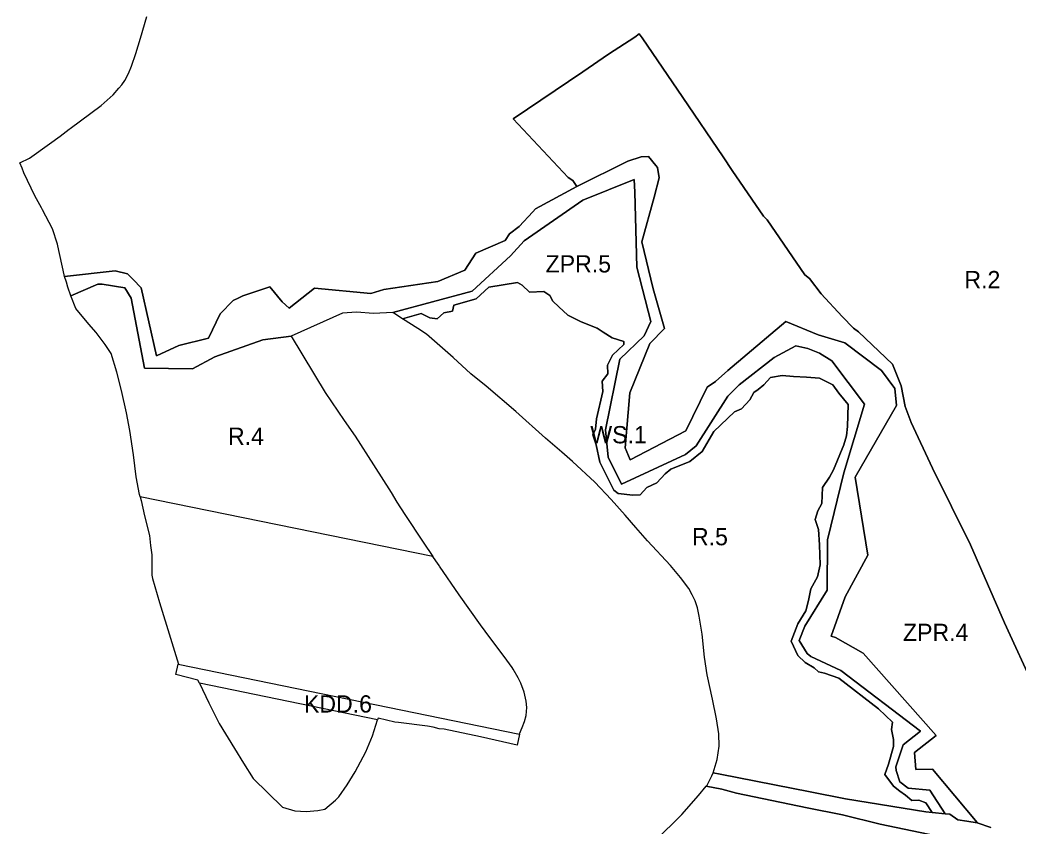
# Model space of a CAD drawing. Extents: x 7422965 to 7424741, y 5551047 to 5553849.
# Drawn here: x 7423072 to 7423766, y 5552892 to 5553453 of the extents above; entities that cross this region are included whole.
import ezdxf

# ---------------------------------------------------------------- set-up
doc = ezdxf.new("R2010")
doc.units = 0
for name, color, linetype in [('linie_rozgraniczajace', 7, 'Continuous'), ('oznaczenia_przeznaczen', 7, 'Continuous'), ('TR_Wydzielone z planu orzeczeniem sądu z 15_07_2011', 7, 'Continuous')]:
    doc.layers.add(name, color=color, linetype=linetype)

msp = doc.modelspace()

# ---------------------------------------------------------------- linework, layer by layer
at = {"layer": 'linie_rozgraniczajace'}
for points in [[(7423072.08, 5553353.5), (7423078.79, 5553356.75), (7423092.7, 5553366.75), (7423100.01, 5553372), (7423106.17, 5553376.96), (7423107.04, 5553377.34), (7423128.51, 5553393.48), (7423136.81, 5553400.87), (7423140.75, 5553405.35), (7423142.84, 5553407.78), (7423144.94, 5553410.78), (7423147.58, 5553415.55), (7423149.53, 5553420.67), (7423152.54, 5553429.58), (7423155.87, 5553440.27), (7423160.29, 5553455.14)], [(7423499.29, 5553440.9), (7423481.05, 5553429.11), (7423463.31, 5553416.76), (7423414.82, 5553384.08), (7423453.09, 5553343.43), (7423456.21, 5553341.18), (7423459.15, 5553337.18), (7423430.34, 5553321.61), (7423428.42, 5553319.38), (7423418.91, 5553309.19), (7423412.34, 5553304.21), (7423409.29, 5553299.45), (7423388.77, 5553290.77), (7423381.2, 5553278.79), (7423362.52, 5553270.91), (7423324.94, 5553265.51), (7423315.78, 5553262.78), (7423276.81, 5553266.37), (7423259.19, 5553252.57), (7423254.3, 5553256.83), (7423245.71, 5553267.27), (7423226.88, 5553260.98), (7423224.13, 5553259.62), (7423220.24, 5553257.7), (7423211.11, 5553248.57), (7423203.06, 5553231.66), (7423182.5, 5553226.56), (7423167, 5553219.27), (7423156.4, 5553266.58), (7423150.84, 5553272.48), (7423146.73, 5553276.28), (7423138.26, 5553278.44), (7423103.11, 5553274.39), (7423102.71, 5553275.62), (7423098.49, 5553295.91), (7423098.27, 5553296.97), (7423094.68, 5553307.7), (7423087.84, 5553320.86), (7423087.11, 5553322.16), (7423082.41, 5553330.54), (7423074.79, 5553346.6), (7423073.55, 5553349.77), (7423072.08, 5553353.5)], [(7423746.77, 5552891.46), (7423737.23, 5552894.78), (7423737.17, 5552894.79), (7423737.17, 5552894.81), (7423706.29, 5552932.02), (7423694.53, 5552931.69), (7423693.58, 5552943.53), (7423708.83, 5552955.35), (7423657.92, 5553012.63), (7423638.79, 5553023.62), (7423635.83, 5553024.45), (7423645.43, 5553051.8), (7423661.31, 5553080.78), (7423652.55, 5553134.99), (7423681.22, 5553184.74), (7423680.11, 5553196.68), (7423670.75, 5553209.05), (7423645.21, 5553228.49), (7423626.82, 5553233.84), (7423604.21, 5553243.11), (7423563.86, 5553209.12), (7423555.48, 5553201.53), (7423549.71, 5553197.54), (7423534.68, 5553167.09), (7423496, 5553147.04), (7423492.62, 5553155.4), (7423495.83, 5553193.64), (7423509.78, 5553227.89), (7423519.98, 5553238.33), (7423512.06, 5553266), (7423504.23, 5553298.7), (7423512.82, 5553329.66), (7423516.18, 5553343.05), (7423515.17, 5553350.25), (7423513.9, 5553351.61), (7423508.83, 5553357.89), (7423503.73, 5553357.8), (7423494.4, 5553354.63), (7423459.15, 5553337.18), (7423456.21, 5553341.18), (7423453.09, 5553343.43), (7423414.82, 5553384.08), (7423463.31, 5553416.76), (7423481.05, 5553429.11), (7423499.29, 5553440.9), (7423502.44, 5553443.28), (7423504.47, 5553440.43), (7423532.63, 5553399.02), (7423560.71, 5553357.68), (7423566.94, 5553348.25), (7423588.8, 5553316.54), (7423591.19, 5553313.83), (7423617.43, 5553275.54), (7423620.71, 5553273.22), (7423628.93, 5553262.45), (7423643.36, 5553246.77), (7423651.33, 5553238.66), (7423654.74, 5553235.94), (7423678.4, 5553213.45), (7423684.3, 5553198.56), (7423687.21, 5553184.11), (7423691.28, 5553172.9), (7423706.1, 5553141.25), (7423732.58, 5553087.91), (7423756.29, 5553033.78), (7423777.38, 5552987.86)], [(7423777.38, 5552987.86), (7423756.29, 5553033.78), (7423732.58, 5553087.91), (7423706.1, 5553141.25), (7423691.28, 5553172.9), (7423687.21, 5553184.11), (7423684.3, 5553198.56), (7423678.4, 5553213.45), (7423654.74, 5553235.94), (7423651.33, 5553238.66), (7423643.36, 5553246.77), (7423628.93, 5553262.45), (7423620.71, 5553273.22), (7423617.43, 5553275.54), (7423591.19, 5553313.83), (7423588.8, 5553316.54), (7423566.94, 5553348.25), (7423560.71, 5553357.68), (7423532.63, 5553399.02), (7423504.47, 5553440.43), (7423502.44, 5553443.28), (7423499.29, 5553440.9)], [(7423103.11, 5553274.39), (7423138.26, 5553278.44), (7423146.73, 5553276.28), (7423150.84, 5553272.48), (7423156.4, 5553266.58), (7423167, 5553219.27), (7423182.5, 5553226.56), (7423203.06, 5553231.66), (7423211.11, 5553248.57), (7423220.24, 5553257.7), (7423224.13, 5553259.62), (7423226.88, 5553260.98), (7423245.71, 5553267.27), (7423254.3, 5553256.83), (7423259.19, 5553252.57), (7423276.81, 5553266.37), (7423315.78, 5553262.78), (7423324.94, 5553265.51), (7423362.52, 5553270.91), (7423381.2, 5553278.79), (7423388.77, 5553290.77), (7423409.29, 5553299.45), (7423412.34, 5553304.21), (7423418.91, 5553309.19), (7423428.42, 5553319.38), (7423430.34, 5553321.61), (7423459.15, 5553337.18), (7423494.4, 5553354.63), (7423503.73, 5553357.8), (7423508.83, 5553357.89), (7423513.9, 5553351.61), (7423515.17, 5553350.25), (7423516.18, 5553343.05), (7423512.82, 5553329.66), (7423504.23, 5553298.7), (7423512.06, 5553266), (7423519.98, 5553238.33), (7423509.78, 5553227.89), (7423495.83, 5553193.64), (7423492.62, 5553155.4), (7423496, 5553147.04), (7423534.68, 5553167.09), (7423549.71, 5553197.54), (7423555.48, 5553201.53), (7423563.86, 5553209.12), (7423604.21, 5553243.11), (7423626.82, 5553233.84), (7423645.21, 5553228.49), (7423670.75, 5553209.05), (7423680.11, 5553196.68), (7423681.22, 5553184.74), (7423652.55, 5553134.99), (7423661.31, 5553080.78), (7423645.43, 5553051.8), (7423635.83, 5553024.45), (7423638.79, 5553023.62), (7423657.92, 5553012.63), (7423708.83, 5552955.35), (7423693.58, 5552943.53), (7423694.53, 5552931.69), (7423706.29, 5552932.02), (7423737.17, 5552894.81), (7423737.17, 5552894.79), (7423730.16, 5552895.83), (7423723.71, 5552896.77), (7423718.19, 5552900.72), (7423715.08, 5552901.03), (7423704.4, 5552917.28), (7423689.29, 5552918.86), (7423683.46, 5552923.12), (7423681.03, 5552931.17), (7423680.69, 5552933.56), (7423685.85, 5552948.93), (7423697.95, 5552958.3), (7423642.42, 5553000.64), (7423621.64, 5553010.34), (7423619.05, 5553012.38), (7423613.61, 5553021.38), (7423617.43, 5553031.41), (7423632.99, 5553056.5), (7423633.28, 5553091.38), (7423644.48, 5553138.05), (7423658.91, 5553185.7), (7423636.16, 5553215.83), (7423627.76, 5553221.3), (7423619.48, 5553224.35), (7423611.24, 5553226.23), (7423596.05, 5553218.24), (7423571.9, 5553199.23), (7423563.87, 5553191.22), (7423541.89, 5553156.73), (7423534.56, 5553150.77), (7423489.97, 5553130.23), (7423480.77, 5553148.83), (7423479.06, 5553167.93), (7423488.95, 5553217.02), (7423505.93, 5553233.3), (7423510.42, 5553243.1), (7423500.63, 5553281.04), (7423499.24, 5553333.06)], [(7423499.24, 5553333.06), (7423498.83, 5553341.99), (7423463.17, 5553327.51), (7423422.36, 5553299.33), (7423412.98, 5553288.93), (7423386.32, 5553264.22), (7423331.17, 5553249.38), (7423317.66, 5553248.75), (7423305.91, 5553249.63), (7423296.3, 5553249), (7423260.61, 5553233.13), (7423240.74, 5553230.4), (7423207.6, 5553218.73), (7423192.02, 5553210.29), (7423158.61, 5553210.78), (7423149.37, 5553259.46), (7423145.05, 5553266.61), (7423129.15, 5553269.23), (7423126.11, 5553269.21), (7423107.43, 5553260.95), (7423105.46, 5553267.09), (7423104.33, 5553270.59), (7423103.11, 5553274.39)], [(7423331.17, 5553249.38), (7423386.32, 5553264.22), (7423412.98, 5553288.93), (7423422.36, 5553299.33), (7423463.17, 5553327.51), (7423498.83, 5553341.99), (7423499.24, 5553333.06), (7423500.63, 5553281.04), (7423510.42, 5553243.1), (7423505.93, 5553233.3), (7423488.95, 5553217.02), (7423479.06, 5553167.93), (7423480.77, 5553148.83), (7423489.97, 5553130.23), (7423534.56, 5553150.77), (7423541.89, 5553156.73), (7423563.87, 5553191.22), (7423571.9, 5553199.23), (7423596.05, 5553218.24), (7423611.24, 5553226.23), (7423619.48, 5553224.35), (7423627.76, 5553221.3), (7423636.16, 5553215.83), (7423658.91, 5553185.7), (7423644.48, 5553138.05), (7423633.28, 5553091.38), (7423632.99, 5553056.5), (7423617.43, 5553031.41), (7423613.61, 5553021.38), (7423619.05, 5553012.38), (7423621.64, 5553010.34), (7423642.42, 5553000.64), (7423697.95, 5552958.3), (7423685.85, 5552948.93), (7423680.69, 5552933.56), (7423681.03, 5552931.17), (7423683.46, 5552923.12), (7423689.29, 5552918.86), (7423704.4, 5552917.28), (7423715.08, 5552901.03), (7423705.89, 5552901.93), (7423701.5, 5552908.62), (7423696.72, 5552910.34), (7423691.72, 5552910.14), (7423687.43, 5552914.03), (7423683.44, 5552916.81), (7423679.15, 5552920.08), (7423672.96, 5552928.39), (7423675.68, 5552935.51), (7423679.19, 5552947.66), (7423678.99, 5552952.66), (7423677.7, 5552959.61), (7423678.5, 5552964.64), (7423668.7, 5552973.89), (7423641.15, 5552995.15), (7423631.08, 5552998.75), (7423627.04, 5552999.59), (7423623.92, 5553002.46), (7423617.77, 5553006.21), (7423612.57, 5553011.01), (7423608.07, 5553020.88), (7423612.68, 5553033.03), (7423618.11, 5553041.99), (7423620.02, 5553049.34), (7423621.69, 5553057.41), (7423626.37, 5553065.61), (7423628.13, 5553074.05), (7423627.76, 5553087.87), (7423627.03, 5553098.66), (7423624.74, 5553105.57), (7423626.5, 5553111.65), (7423629.29, 5553116.77), (7423629.85, 5553127.8), (7423634.56, 5553134.99), (7423637.35, 5553140.11), (7423644.48, 5553157.54), (7423646.52, 5553163.71), (7423647.06, 5553170.22), (7423647.52, 5553185.56), (7423641.2, 5553193.31), (7423636.96, 5553199.14), (7423627.77, 5553203.77), (7423618.73, 5553204.41), (7423609.7, 5553205.04), (7423601.67, 5553205.72), (7423593.71, 5553204.39), (7423588.92, 5553199.19), (7423585.05, 5553196.03), (7423582.13, 5553193.91), (7423579.34, 5553188.8), (7423573.58, 5553182.56), (7423568.67, 5553180.36), (7423554.21, 5553166.76), (7423546.2, 5553152.9), (7423537.6, 5553145.9), (7423524.25, 5553140.53), (7423520.38, 5553137.37), (7423514.62, 5553131.13), (7423507.75, 5553127.85), (7423502.96, 5553122.65)], [(7423502.96, 5553122.65), (7423497.96, 5553122.45), (7423487.65, 5553123.65), (7423484.66, 5553125.88), (7423475.01, 5553145.53), (7423472.52, 5553157.44), (7423470.24, 5553164.36), (7423472.08, 5553168.43), (7423472.79, 5553175.47), (7423477.02, 5553194.65), (7423476.74, 5553201.65), (7423480.53, 5553206.81), (7423480.29, 5553212.8), (7423483.72, 5553219.9), (7423491.71, 5553227.27), (7423491.63, 5553229.27), (7423483.51, 5553231.95), (7423477.36, 5553235.7), (7423473.24, 5553238.53), (7423462.04, 5553243.08), (7423452.85, 5553247.71), (7423446.61, 5553253.47), (7423442.45, 5553257.3), (7423440.29, 5553261.22), (7423436.17, 5553264.05), (7423426.18, 5553263.65), (7423420.99, 5553268.44), (7423417.91, 5553270.32), (7423397.83, 5553267.12), (7423389.16, 5553259.08), (7423373.51, 5553254.5), (7423372.68, 5553250.47), (7423366.72, 5553249.22), (7423361.89, 5553245.03), (7423356.85, 5553245.82), (7423350.79, 5553248.7), (7423338, 5553245.08), (7423331.17, 5553249.38)], [(7423338, 5553245.08), (7423350.79, 5553248.7), (7423356.85, 5553245.82), (7423361.89, 5553245.03), (7423366.72, 5553249.22), (7423372.68, 5553250.47), (7423373.51, 5553254.5), (7423389.16, 5553259.08), (7423397.83, 5553267.12), (7423417.91, 5553270.32), (7423420.99, 5553268.44), (7423426.18, 5553263.65), (7423436.17, 5553264.05), (7423440.29, 5553261.22), (7423442.45, 5553257.3), (7423446.61, 5553253.47), (7423452.85, 5553247.71), (7423462.04, 5553243.08), (7423473.24, 5553238.53), (7423477.36, 5553235.7), (7423483.51, 5553231.95), (7423491.63, 5553229.27), (7423491.71, 5553227.27), (7423483.72, 5553219.9), (7423480.29, 5553212.8), (7423480.53, 5553206.81), (7423476.74, 5553201.65), (7423477.02, 5553194.65), (7423472.79, 5553175.47), (7423472.08, 5553168.43), (7423470.24, 5553164.36), (7423472.52, 5553157.44), (7423475.01, 5553145.53), (7423484.66, 5553125.88), (7423487.65, 5553123.65), (7423497.96, 5553122.45), (7423502.96, 5553122.65), (7423507.75, 5553127.85), (7423514.62, 5553131.13), (7423520.38, 5553137.37), (7423524.25, 5553140.53), (7423537.6, 5553145.9), (7423546.2, 5553152.9), (7423554.21, 5553166.76), (7423568.67, 5553180.36), (7423573.58, 5553182.56), (7423579.34, 5553188.8), (7423582.13, 5553193.91), (7423585.05, 5553196.03), (7423588.92, 5553199.19), (7423593.71, 5553204.39), (7423601.67, 5553205.72), (7423609.7, 5553205.04), (7423618.73, 5553204.41), (7423627.77, 5553203.77), (7423636.96, 5553199.14), (7423641.2, 5553193.31), (7423647.52, 5553185.56), (7423647.06, 5553170.22), (7423646.52, 5553163.71), (7423644.48, 5553157.54), (7423637.35, 5553140.11), (7423634.56, 5553134.99), (7423629.85, 5553127.8), (7423629.29, 5553116.77), (7423626.5, 5553111.65), (7423624.74, 5553105.57), (7423627.03, 5553098.66), (7423627.76, 5553087.87), (7423628.13, 5553074.05), (7423626.37, 5553065.61), (7423621.69, 5553057.41), (7423620.02, 5553049.34), (7423618.11, 5553041.99), (7423612.68, 5553033.03), (7423608.07, 5553020.88), (7423612.57, 5553011.01), (7423617.77, 5553006.21), (7423623.92, 5553002.46), (7423627.04, 5552999.59), (7423631.08, 5552998.75), (7423641.15, 5552995.15), (7423668.7, 5552973.89), (7423678.5, 5552964.64), (7423677.7, 5552959.61), (7423678.99, 5552952.66), (7423679.19, 5552947.66), (7423675.68, 5552935.51), (7423672.96, 5552928.39), (7423679.15, 5552920.08), (7423683.44, 5552916.81), (7423687.43, 5552914.03), (7423691.72, 5552910.14), (7423696.72, 5552910.34), (7423701.5, 5552908.62), (7423705.89, 5552901.93), (7423701.59, 5552902.35), (7423645.66, 5552911.28), (7423621.2, 5552916.25), (7423558.75, 5552928.42)], [(7423558.75, 5552928.42), (7423553.83, 5552929.37), (7423556.61, 5552938.72), (7423557.91, 5552947.91), (7423557.74, 5552956.57), (7423556.05, 5552966.94), (7423553.21, 5552980.72), (7423549.54, 5552997.52), (7423547.72, 5553009.92), (7423546.02, 5553025.9), (7423544.08, 5553038.47), (7423542.87, 5553044.16), (7423541.28, 5553049.05), (7423539.07, 5553053.18), (7423536.81, 5553057.65), (7423531.05, 5553065.18), (7423524.2, 5553073.59), (7423508.12, 5553090.82), (7423500.04, 5553099.89), (7423492.7, 5553108.46), (7423482.79, 5553119.48), (7423471.51, 5553131.58), (7423455.95, 5553145.89), (7423448.58, 5553152.28), (7423437.28, 5553162.19), (7423416.72, 5553180.56), (7423395.96, 5553198.29), (7423385.36, 5553206.91), (7423373.19, 5553218.15), (7423354.64, 5553234.51), (7423348.58, 5553238.42), (7423338, 5553245.08)], [(7423714.41, 5552884.41), (7423669.78, 5552893.7), (7423643.59, 5552900.3), (7423619.1, 5552905.09), (7423569.98, 5552915.38), (7423559.76, 5552918.11), (7423549.01, 5552920.19), (7423549.55, 5552920.84), (7423550.71, 5552923.18), (7423552.95, 5552927.44), (7423553.83, 5552929.37), (7423558.75, 5552928.42), (7423621.2, 5552916.25), (7423645.66, 5552911.28), (7423701.59, 5552902.35), (7423705.89, 5552901.93), (7423715.08, 5552901.03), (7423718.19, 5552900.72), (7423723.71, 5552896.77), (7423730.16, 5552895.83), (7423737.17, 5552894.79), (7423737.23, 5552894.78), (7423746.77, 5552891.46)], [(7423514.86, 5552883.69), (7423525.29, 5552893.69), (7423531.95, 5552900.48), (7423543.59, 5552913.6), (7423549.01, 5552920.19), (7423559.76, 5552918.11), (7423569.98, 5552915.38), (7423619.1, 5552905.09), (7423643.59, 5552900.3), (7423669.78, 5552893.7), (7423714.41, 5552884.41)]]:
    msp.add_lwpolyline(points, dxfattribs=at)
for points in [[(7423107.43, 5553260.95), (7423126.11, 5553269.21), (7423129.15, 5553269.23), (7423145.05, 5553266.61), (7423149.37, 5553259.46), (7423158.61, 5553210.78), (7423192.02, 5553210.29), (7423207.6, 5553218.73), (7423240.74, 5553230.4), (7423260.61, 5553233.13), (7423284.06, 5553193.93), (7423297.42, 5553174.49), (7423304.93, 5553163.43), (7423317.74, 5553143.61), (7423330.02, 5553124.24), (7423334.05, 5553117.72), (7423339.53, 5553108.98), (7423352.32, 5553089.91), (7423359.09, 5553079.84), (7423155.59, 5553121.43), (7423155.26, 5553122.9), (7423152.74, 5553135.14), (7423151.04, 5553150.63), (7423148.48, 5553167.53), (7423146.06, 5553179.65), (7423142.69, 5553195.18), (7423139.32, 5553207.91), (7423135.55, 5553220.95), (7423131.39, 5553227.24), (7423125.12, 5553235.59), (7423119.91, 5553241.44), (7423110.84, 5553252.33)], [(7423180.32, 5552997.79), (7423182.09, 5553004.88), (7423419.2, 5552956.42), (7423417.66, 5552948.69), (7423392.04, 5552954.55), (7423366.83, 5552959.83), (7423363.32, 5552959.96), (7423359.3, 5552961.15), (7423355.35, 5552961.93), (7423335.03, 5552964.42), (7423332.53, 5552964.75), (7423320.93, 5552967.56), (7423320.56, 5552966.37), (7423196.79, 5552991.67), (7423195.75, 5552993.8)]]:
    msp.add_lwpolyline(points, close=True, dxfattribs=at)
at = {"layer": 'TR_Wydzielone z planu orzeczeniem sądu z 15_07_2011'}
for p, q in [((7423359.09, 5553079.84), (7423155.59, 5553121.43)), ((7423155.59, 5553121.43), (7423156.19, 5553118.71)), ((7423361.12, 5553076.82), (7423359.09, 5553079.84)), ((7423182.09, 5553004.88), (7423419.2, 5552956.42)), ((7423320.56, 5552966.37), (7423196.79, 5552991.67)), ((7423196.79, 5552991.67), (7423203.37, 5552978.22))]:
    msp.add_line(p, q, dxfattribs=at)
for points in [[(7423156.19, 5553118.71), (7423158.52, 5553108.17), (7423161.99, 5553094.4), (7423162.85, 5553087.44), (7423163.64, 5553081.04), (7423163.78, 5553066.83), (7423164.12, 5553064.6), (7423169.03, 5553047.84), (7423176.75, 5553023.18), (7423182.13, 5553005.02), (7423182.09, 5553004.88)], [(7423419.2, 5552956.42), (7423419.24, 5552956.63), (7423421.15, 5552960.86), (7423422.76, 5552965.21), (7423423.9, 5552969.33), (7423424.28, 5552974.87), (7423423.85, 5552979.37), (7423422.4, 5552985.56), (7423420.16, 5552991.72), (7423418.18, 5552995.51), (7423414.88, 5553001.46), (7423414.05, 5553002.6), (7423408.55, 5553010.21), (7423398.68, 5553023.54), (7423392.03, 5553032.39), (7423377.26, 5553053.22), (7423363.65, 5553073.07), (7423363.28, 5553073.61), (7423361.12, 5553076.82)], [(7423203.37, 5552978.22), (7423210.49, 5552963.81), (7423221.13, 5552946.45), (7423227.45, 5552936.27), (7423234.24, 5552925.6), (7423254.43, 5552905.54), (7423263.18, 5552902.97), (7423270.85, 5552902.49), (7423279.03, 5552903.25), (7423283.92, 5552904.3), (7423291.38, 5552910.44), (7423293.65, 5552912.71), (7423299.5, 5552921.16), (7423305.11, 5552930.17), (7423312.33, 5552944.12), (7423317.14, 5552955.21), (7423320.56, 5552966.37)]]:
    msp.add_lwpolyline(points, dxfattribs=at)

# ---------------------------------------------------------------- texts
at = {"layer": 'oznaczenia_przeznaczen'}
for s, p in [('ZPR.5', (7423437.34, 5553277.29)), ('R.2', (7423728.36, 5553266.37)), ('R.4', (7423216.64, 5553157.47)), ('WS.1', (7423468.42, 5553158.51)), ('R.5', (7423539.04, 5553087.64)), ('ZPR.4', (7423685.67, 5553021.07)), ('KDD.6', (7423269.42, 5552971.36))]:
    msp.add_text(s, height=12, dxfattribs=at).set_placement(p)

doc.saveas('drawing.dxf')
